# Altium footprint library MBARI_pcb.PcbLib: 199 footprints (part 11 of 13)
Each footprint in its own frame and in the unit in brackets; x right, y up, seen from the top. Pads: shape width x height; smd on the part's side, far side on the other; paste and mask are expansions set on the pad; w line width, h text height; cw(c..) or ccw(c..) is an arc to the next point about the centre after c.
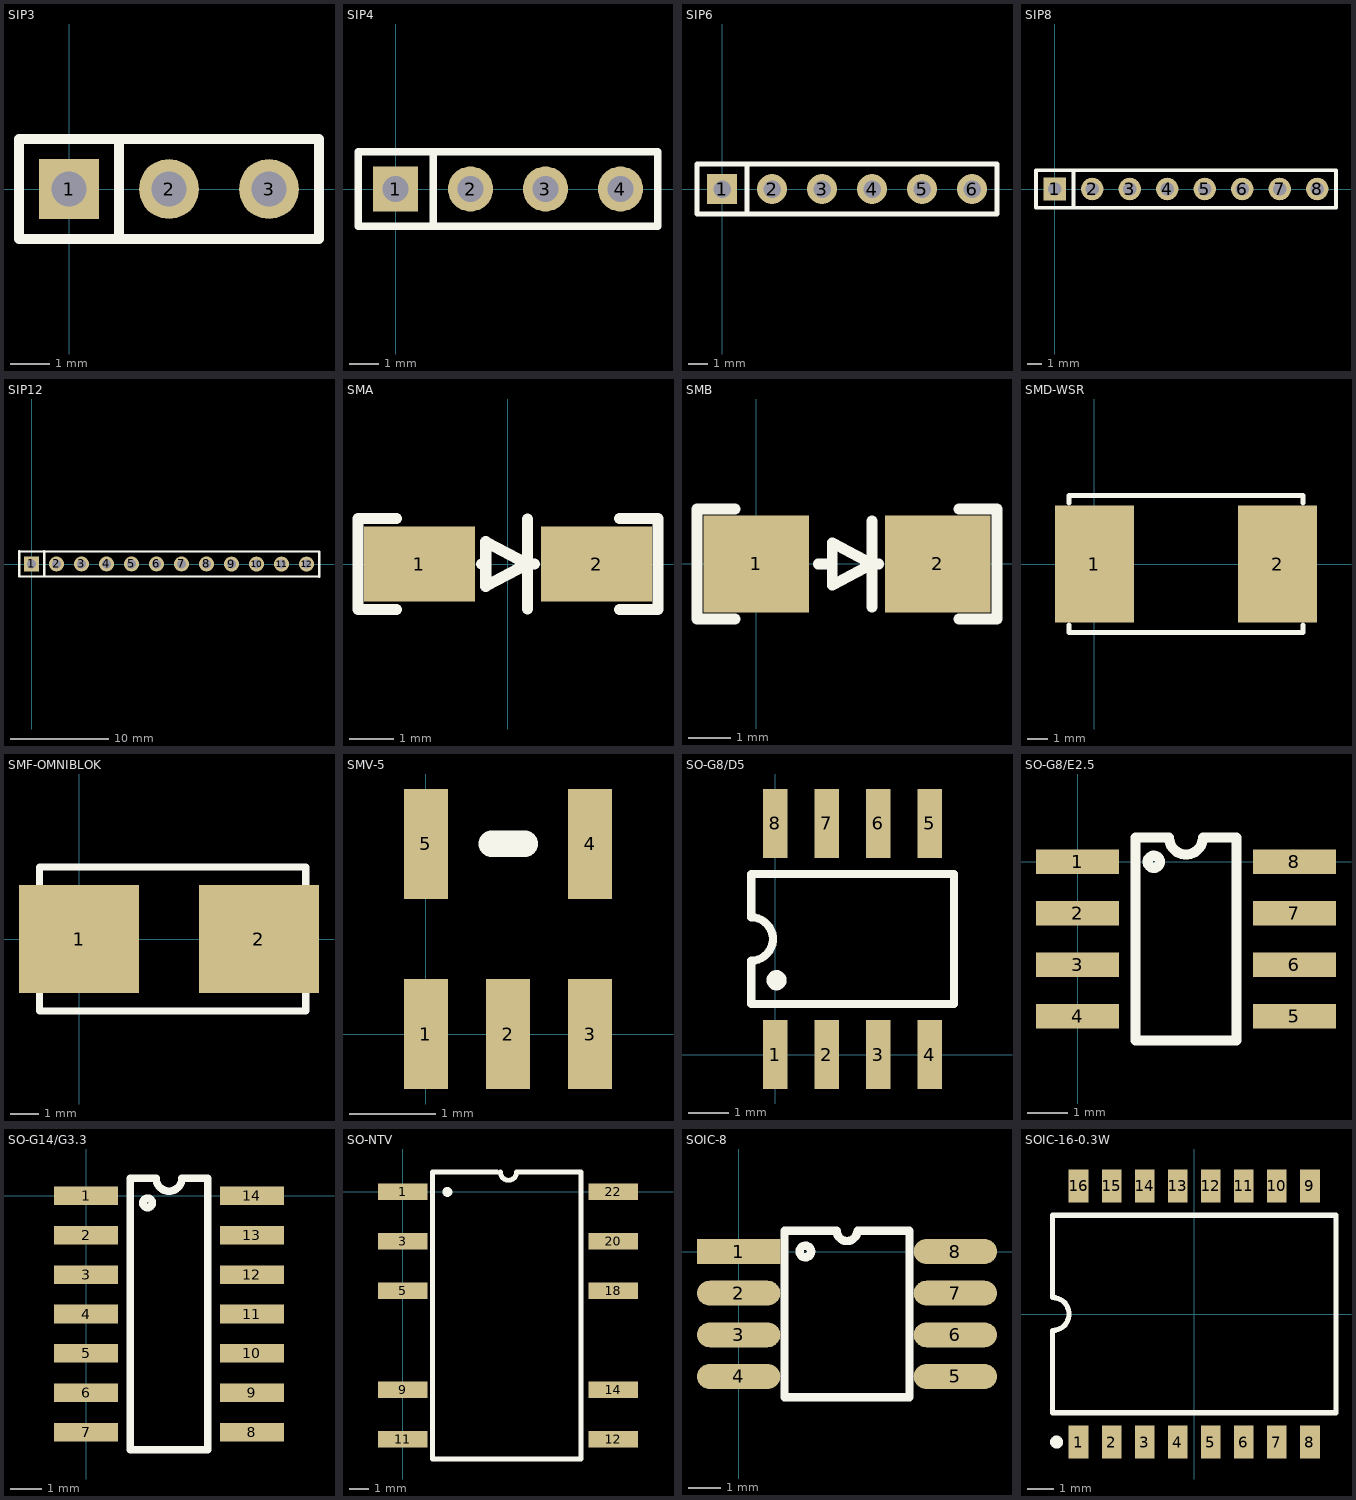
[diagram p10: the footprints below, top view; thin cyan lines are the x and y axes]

## SIP3 [mil]
pads (3):
  rect 60x60 hole 35: 1(0,0)
  round 60 hole 35: 2(100,0) 3(200,0)
TopOverlay:
  lines w10: 50,-50 50,50 ; -50,-50 -50,50 250,50 250,-50 -50,-50

## SIP4 [mil]
pads (4):
  rect 60x60 hole 35: 1(0,0)
  round 60 hole 35: 2(100,0) 3(200,0) 4(300,0)
TopOverlay:
  lines w10: 50,-50 50,50 ; -50,-50 350,-50 350,50 -50,50 -50,-50

## SIP6 [mil]
pads (6):
  rect 60x60 hole 35: 1(0,0)
  round 60 hole 35: 2(100,0) 3(200,0) 4(300,0) 5(400,0) 6(500,0)
TopOverlay:
  lines w10: 50,-50 50,50 ; -50,-50 -50,50 550,50 550,-50 -50,-50

## SIP8 [mil]
pads (8):
  rect 60x60 hole 35: 1(0,0.38)
  round 60 hole 35: 2(100,0.38) 3(200,0.38) 4(300,0.38) 5(400,0.38) 6(500,0.38) 7(600,0.38) 8(700,0.38)
TopOverlay:
  lines w10: 50,-49.62 50,50.38 ; -50,-49.62 -50,50.38 750,50.38 750,-49.62 -50,-49.62

## SIP12 [mil] "12 position SIP"
pads (12):
  rect 60x60 hole 35: 1(0,0.38)
  round 60 hole 35: 2(100,0.38) 3(200,0.38) 4(300,0.38) 5(400,0.38) 6(500,0.38) 7(600,0.38) 8(700,0.38) 9(800,0) 10(900,0) 11(1000,0) 12(1100,0)
TopOverlay:
  lines w10: 50,-49.62 50,50.38 ; -50,-49.62 -50,50.38 1150,50 1150,-50 -50,-49.62

## SMA [mm] "SMA Diode"
pads (2):
  rect 2.5x1.7 smd: 1(-2,0) 2(2,0)
TopOverlay:
  lines w0.254: -2.522,-1.024 -3.384,-1.024 -3.384,1.024 -2.522,1.024 ; -0.6,0 -0.576,0 ; 0.44,-1.016 0.44,1.016 ; 0.6,0 0.44,0 ; 2.522,-1.024 3.384,-1.024 3.384,1.024 2.522,1.024 ; 0.44,0 -0.5,-0.5 -0.5,0.5 0.44,0

## SMB [mm] "SMB Diode"
pads (2):
  rect 2.5x2.3 smd: 1(0,0) 2(4.3,0)
TopOverlay:
  lines w0.254: -0.5,-1.3 -1.4,-1.3 -1.4,1.3 -0.5,1.3 ; 1.47,0 1.724,0 ; 2.74,-1.016 2.74,1.016 ; 2.9,0 2.74,0 ; 4.8,-1.3 5.7,-1.3 5.7,1.3 4.8,1.3 ; 2.74,0 1.8,0.5 1.8,-0.5 2.74,0

## SMD-WSR [mil]
pads (2):
  rect 155x230 smd: 1(0,0) 2(360,0)
TopOverlay:
  lines w10: -50,-120 -50,-135 410,-135 410,-120 ; -50,120 -50,135 410,135 410,120

## SMF-OMNIBLOK [mil] "SMD Nano Fuse Holder"
height 150
pads (2):
  rect 167x150 smd: 1(0,0) 2(250,0)
TopOverlay:
  lines w10: -55,-75 -55,-100 315,-100 315,-75 ; -55,75 -55,100 315,100 315,75

## SMV-5 [mil]
pads (5):
  rect 20x50 smd: 1(0,0) 2(37.4,0) 3(74.8,0) 4(74.8,86.61) 5(0,86.61)
TopOverlay:
  lines w12: 30,86.61 45,86.61

## SO-G8/D5 [mm]
pads (8):
  rect 0.6x1.7 smd: 1(0,0) 2(1.27,0) 3(2.54,0) 4(3.81,0) 5(3.81,5.7) 6(2.54,5.7) 7(1.27,5.7) 8(0,5.7)
TopOverlay:
  circle w0.25: c0.027,1.834 r0.125
  lines w0.2: -0.595,2.317 ccw(c-0.595,2.85) -0.595,3.383 -0.595,4.45 4.405,4.45 4.405,1.25 -0.595,1.25 -0.595,2.317

## SO-G8/E2.5 [mm]
pads (8):
  rect 2.05x0.6 smd: 1(0,0) 2(0,-1.27) 3(0,-2.54) 4(0,-3.81) 5(5.35,-3.81) 6(5.35,-2.54) 7(5.35,-1.27) 8(5.35,0)
TopOverlay:
  circle w0.25: c1.882,0 r0.15
  lines w0.25: 2.258,0.595 1.425,0.595 1.425,-4.405 3.925,-4.405 3.925,0.595 3.092,0.595 cw(c2.675,0.595) 2.258,0.595

## SO-G14/G3.3 [mm]
pads (14):
  rect 2.05x0.6 smd: 1(0,0) 2(0,-1.27) 3(0,-2.54) 4(0,-3.81) 5(0,-5.08) 6(0,-6.35) 7(0,-7.62) 8(5.35,-7.62) 9(5.35,-6.35) 10(5.35,-5.08) 11(5.35,-3.81) 12(5.35,-2.54) 13(5.35,-1.27) 14(5.35,0)
TopOverlay:
  circle w0.25: c1.984,-0.229 r0.15
  lines w0.25: 1.425,-8.185 3.925,-8.185 3.925,0.565 3.092,0.565 cw(c2.675,0.565) 2.258,0.565 1.425,0.565 1.425,-8.185

## SO-NTV [mm]
pads (10):
  rect 2.54x0.85 smd: 1(0,0) 3(0,-2.54) 5(0,-5.08) 9(0,-10.16) 11(0,-12.7) 12(10.8,-12.7) 14(10.8,-10.16) 18(10.8,-5.08) 20(10.8,-2.54) 22(10.8,0)
TopOverlay:
  circle w0.254: c2.286,0 r0.127
  lines w0.25: 5.009,1.016 ccw(c5.425,1.016) 5.842,1.016
  lines w0.254: 4.826,1.016 1.524,1.016 1.524,-13.716 9.144,-13.716 9.144,1.016 5.842,1.016

## SOIC-8 [mil]
pads (8):
  rect 100x30 smd: 1(0,0)
  oval 100x30 smd: 2(0,-50) 3(0,-100) 4(0,-150) 5(260,-150) 6(260,-100) 7(260,-50) 8(260,0)
TopOverlay:
  circle w10: c80,0 r7
  lines w10: 55,-175 55,25 117.5,25 ccw(c130,25) 142.5,25 205,25 205,-175 55,-175

## SOIC-16-0.3W [mil] "LTC SW pkg DWG# 05-08-1620"
height 100
pads (16):
  rect 30x50 smd: 1(-175,-193.9) 2(-125,-193.9) 3(-75,-193.9) 4(-25,-193.9) 5(25,-193.9) 6(75,-193.9) 7(125,-193.9) 8(175,-193.9) 9(175,193.9) 10(125,193.9) 11(75,193.9) 12(25,193.9) 13(-25,193.9) 14(-75,193.9) 15(-125,193.9) 16(-175,193.9)
TopOverlay:
  circle w9.84: c-208.46,-193.9 r4.92
  lines w7.87: -214.57,-149.61 214.57,-149.61 214.57,149.61 -214.57,149.61 -214.57,25 cw(c-214.57,0) -214.57,-25 -214.57,-149.61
